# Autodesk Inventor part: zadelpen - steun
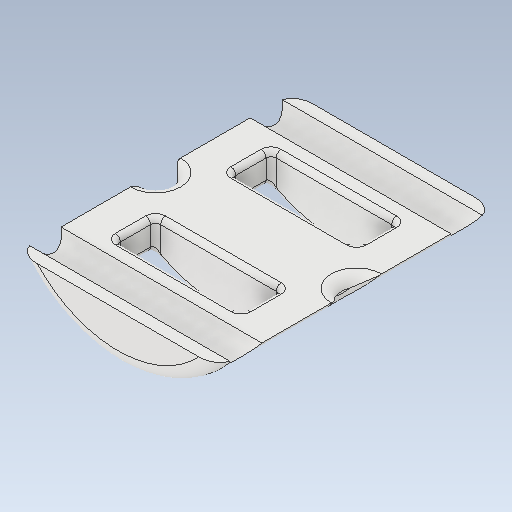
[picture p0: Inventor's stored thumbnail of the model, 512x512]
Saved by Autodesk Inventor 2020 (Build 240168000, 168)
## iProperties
Created: 2017-11
Part Number: zadelpen - steun
Material: Ogólny
Document SubType Name: Modeling
Designer: Tomasz
Density: 1 g/cm^3
Appearance: Domyślna
Author: Tomasz
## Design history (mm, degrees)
feature "Solid1"
node "Bryła1"
